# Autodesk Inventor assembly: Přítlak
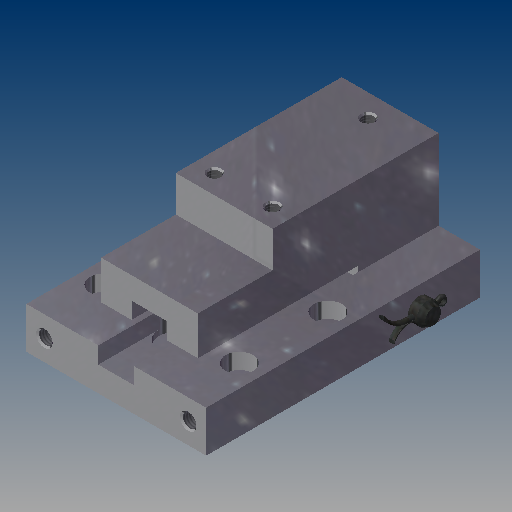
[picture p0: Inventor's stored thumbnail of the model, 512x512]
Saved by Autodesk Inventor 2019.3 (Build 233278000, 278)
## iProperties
Created: 2019-01
Part Number: Přítlak
Material: Všeobecné
Document SubType Name: Assembly
Designer: B-hon
Author: B-hon
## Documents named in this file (5)
- C:\Users\B-hon\OneDrive\Plocha\Bakalářka22\Přítlak\Pravý\Přítlak1h.iam
- C:\Users\B-hon\OneDrive\Plocha\Bakalářka22\Přítlak\Pravý\Příruba vozíku1h.ipt
- C:\Users\B-hon\OneDrive\Plocha\Bakalářka22\Přítlak\Pravý\Příruba desky1h.ipt
- C:\Users\B-hon\OneDrive\Documents\Inventor\Content Center Files\R2019\cs-CZ\BS EN 22 341  B\ISO 2341 - B - 8 x 70BS EN.ipt
- C:\Users\B-hon\OneDrive\Documents\Inventor\Content Center Files\R2019\cs-CZ\CSN EN ISO 1234\CSN EN ISO 1234 - 2x16 x 10 - 9.ipt
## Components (4 placed, 4 different names)
1. Příruba vozíku1h:1 — Vložit:1, Vložit:2, Úhel:1
2. Příruba desky1h:1 — Vložit:1, Úhel:1
3. BS EN 22341 B B - 8 x 70:1 — Vložit:2, Proti sobě:3
4. CSN EN ISO 1234 2x16:1 — Proti sobě:3
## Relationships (4: Insert 2, Mate 1, Angle 1)
- Vložit:1 [Insert]: Příruba vozíku1h:1 ↔ Příruba desky1h:1
- Vložit:2 [Insert]: Příruba vozíku1h:1 ↔ BS EN 22341 B B - 8 x 70:1
- Proti sobě:3 [Mate]: BS EN 22341 B B - 8 x 70:1 ↔ CSN EN ISO 1234 2x16:1
- Úhel:1 [Angle]: Příruba vozíku1h:1 ↔ Příruba desky1h:1
